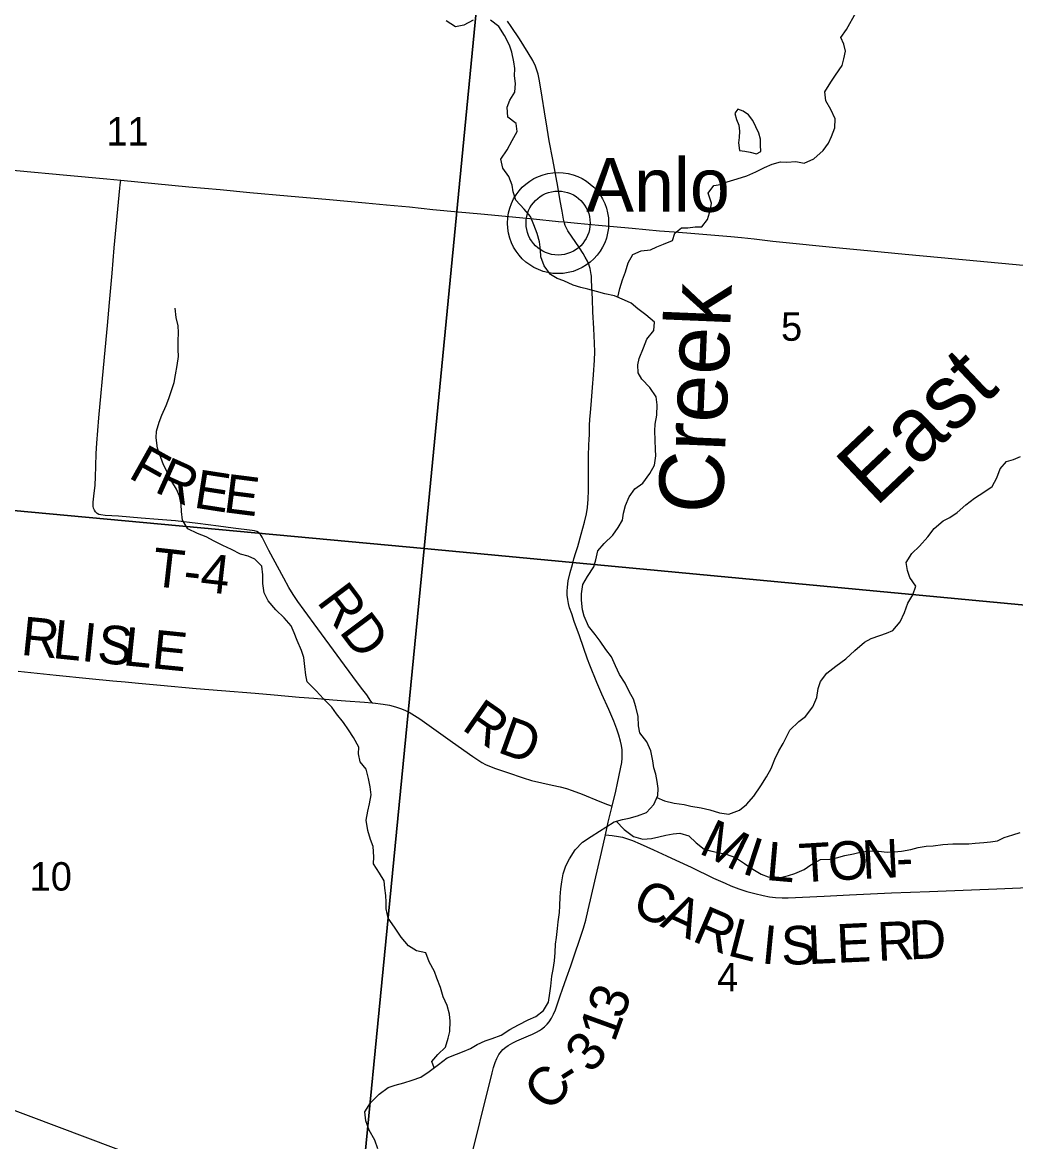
# Model space of a CAD drawing. Extents: x 831 to 1552, y 430 to 870.
# Drawn here: x 1297.57 to 1326.79, y 727.92 to 760.87 of the extents above; entities that cross this region are included whole.
import ezdxf

# ---------------------------------------------------------------- set-up
doc = ezdxf.new("R2010")
doc.units = 0
for name, color, linetype in [('GM_X_Corporation', 7, 'Continuous'), ('GM_X_County_Road', 7, 'Continuous'), ('GM_X_County_Road_Text', 7, 'Continuous'), ('GM_X_Minor_Lake', 7, 'Continuous'), ('GM_X_Minor_River', 7, 'Continuous'), ('GM_X_Minor_River_Text', 7, 'Continuous'), ('GM_X_Section_Text', 7, 'Continuous'), ('GM_X_Township_Road', 7, 'Continuous'), ('GM_X_Township_Road_Text', 7, 'Continuous'), ('GM_X_Unincorporated', 7, 'Continuous'), ('GM_X_Unincorporated_Location', 7, 'Continuous'), ('GM_X_Unincorporated_Text', 7, 'Continuous'), ('SH_Text', 7, 'Continuous')]:
    doc.layers.add(name, color=color, linetype=linetype)

msp = doc.modelspace()

# ---------------------------------------------------------------- linework, layer by layer
at = {"layer": 'GM_X_Corporation'}
for points in [[(1291.379, 767.224), (1311.293, 765.037), (1309.391, 745.383), (1289.554, 747.22)], [(1311.293, 765.037), (1331.382, 763.355), (1329.567, 743.48), (1309.391, 745.383)], [(1289.554, 747.22), (1309.391, 745.383), (1307.365, 724.655), (1287.469, 726.554)], [(1309.391, 745.383), (1329.567, 743.48), (1327.468, 722.912), (1307.365, 724.655)]]:
    msp.add_lwpolyline(points, close=True, dxfattribs=at)
at = {"layer": 'GM_X_County_Road'}
for points in [[(1313.508, 754.996), (1313.49, 755.073), (1313.445, 755.306), (1313.391, 755.611), (1313.32, 756.04), (1313.174, 756.833), (1313.069, 757.382), (1313.007, 757.749), (1312.925, 758.236), (1312.857, 758.668), (1312.783, 759.149), (1312.764, 759.244), (1312.74, 759.343), (1312.707, 759.463), (1312.665, 759.581), (1312.584, 759.745), (1312.446, 759.967), (1312.188, 760.38), (1311.95, 760.751), (1311.842, 760.905)], [(1280.671, 758.126), (1280.82, 758.113), (1281.871, 758.011), (1282.798, 757.914), (1284.097, 757.789), (1285.044, 757.707), (1285.828, 757.627), (1287.312, 757.483), (1288.055, 757.415), (1289.166, 757.314), (1289.731, 757.266), (1290.465, 757.198), (1291.083, 757.133), (1292.012, 757.043), (1292.815, 756.958), (1294.175, 756.821), (1295.782, 756.662), (1296.524, 756.591), (1297.391, 756.511), (1298.875, 756.37), (1300.05, 756.259), (1300.461, 756.22)], [(1300.461, 756.22), (1302.462, 756.031), (1303.39, 755.944), (1304.256, 755.863), (1305.37, 755.762), (1306.607, 755.652), (1307.659, 755.553), (1308.277, 755.494), (1308.957, 755.433), (1309.646, 755.361), (1310.386, 755.29), (1311.052, 755.228), (1312.603, 755.081), (1313.345, 755.011), (1313.508, 754.996)], [(1314.918, 737.795), (1315.023, 738.233), (1315.073, 738.472), (1315.167, 738.896), (1315.204, 739.081), (1315.216, 739.206), (1315.217, 739.332), (1315.209, 739.457), (1315.191, 739.581), (1315.166, 739.704), (1315.115, 739.885), (1315.055, 740.062), (1314.965, 740.294), (1314.819, 740.638), (1314.613, 741.09), (1314.465, 741.431), (1314.262, 741.949), (1314.194, 742.122), (1313.955, 742.809), (1313.804, 743.23), (1313.728, 743.457), (1313.667, 743.633), (1313.633, 743.758), (1313.612, 743.879), (1313.599, 744.002), (1313.597, 744.12), (1313.605, 744.245), (1313.629, 744.431), (1313.684, 744.67), (1313.748, 744.909), (1313.796, 745.076), (1313.851, 745.262), (1313.906, 745.44), (1314.008, 745.804), (1314.107, 746.157), (1314.16, 746.401), (1314.19, 746.586), (1314.213, 746.834), (1314.223, 747.084), (1314.224, 747.457), (1314.227, 748.077), (1314.235, 748.449), (1314.24, 748.573), (1314.249, 748.757), (1314.256, 749.003), (1314.266, 749.188), (1314.283, 749.376), (1314.311, 749.741), (1314.343, 750.117), (1314.372, 750.488), (1314.398, 750.922), (1314.407, 751.172), (1314.403, 751.421), (1314.383, 751.855), (1314.355, 752.347), (1314.338, 752.717), (1314.315, 753.276), (1314.313, 753.338), (1314.307, 753.395), (1314.3, 753.45), (1314.29, 753.507), (1314.279, 753.565), (1314.268, 753.62), (1314.251, 753.685), (1314.228, 753.747), (1314.19, 753.836), (1314.124, 753.961), (1314.067, 754.063), (1313.959, 754.232), (1313.618, 754.734), (1313.584, 754.793), (1313.557, 754.847), (1313.538, 754.891), (1313.518, 754.955), (1313.508, 754.996)], [(1313.508, 754.996), (1313.902, 754.958), (1314.52, 754.899), (1315.51, 754.81), (1316.315, 754.736), (1316.748, 754.701), (1317.119, 754.672), (1318.415, 754.564), (1318.724, 754.536), (1319.094, 754.496), (1319.65, 754.432), (1320.33, 754.363), (1321.009, 754.292), (1321.503, 754.241), (1322.431, 754.151), (1323.544, 754.044), (1324.596, 753.945), (1328.059, 753.623), (1328.678, 753.565), (1329.111, 753.524), (1329.544, 753.485), (1330.044, 753.438), (1330.507, 753.392)], [(1297.445, 741.77), (1298.557, 741.652), (1299.532, 741.552), (1300.225, 741.489), (1300.593, 741.455), (1300.986, 741.418), (1301.632, 741.357), (1302.684, 741.261), (1303.427, 741.202), (1304.414, 741.118), (1304.971, 741.068), (1305.713, 741.007), (1306.146, 740.97), (1306.703, 740.926), (1307.075, 740.899), (1307.63, 740.856), (1307.857, 740.835)], [(1307.857, 740.835), (1307.877, 740.833), (1308.185, 740.799), (1308.367, 740.769), (1308.547, 740.724), (1308.722, 740.664), (1308.835, 740.616), (1308.944, 740.56), (1309.104, 740.466), (1309.259, 740.364), (1310.222, 739.681), (1310.824, 739.256), (1311.084, 739.085), (1311.194, 739.025), (1311.308, 738.972), (1311.483, 738.906), (1311.835, 738.784), (1312.305, 738.626), (1312.544, 738.554), (1312.847, 738.48), (1313.151, 738.418), (1313.393, 738.365), (1313.571, 738.316), (1313.746, 738.256), (1314.034, 738.145), (1314.552, 737.934), (1314.784, 737.846), (1314.918, 737.795)], [(1314.719, 736.953), (1314.805, 737.324), (1314.918, 737.795)], [(1310.828, 727.698), (1310.966, 728.237), (1311.098, 728.77), (1311.241, 729.349), (1311.388, 729.948), (1311.431, 730.101), (1311.479, 730.248), (1311.526, 730.368), (1311.558, 730.431), (1311.588, 730.483), (1311.622, 730.535), (1311.662, 730.583), (1311.706, 730.629), (1311.794, 730.704), (1311.862, 730.752), (1311.992, 730.825), (1312.111, 730.885), (1312.457, 731.03), (1312.572, 731.083), (1312.69, 731.138), (1312.779, 731.188), (1312.843, 731.234), (1312.93, 731.303), (1313.004, 731.374), (1313.068, 731.449), (1313.139, 731.557), (1313.194, 731.672), (1313.248, 731.803), (1313.29, 731.917), (1313.345, 732.064), (1313.393, 732.213), (1313.46, 732.412), (1313.576, 732.741), (1313.699, 733.099), (1313.818, 733.448), (1313.956, 733.855), (1314.073, 734.207), (1314.143, 734.443), (1314.218, 734.743), (1314.409, 735.59), (1314.606, 736.435), (1314.719, 736.953)], [(1314.719, 736.953), (1314.92, 736.93), (1315.103, 736.904), (1315.223, 736.878), (1315.341, 736.845), (1315.514, 736.785), (1315.74, 736.691), (1316.134, 736.513), (1316.517, 736.336), (1316.795, 736.206), (1317.243, 735.996), (1317.905, 735.678), (1318.239, 735.524), (1318.41, 735.451), (1318.642, 735.363), (1318.879, 735.287), (1319.119, 735.221), (1319.36, 735.163), (1319.544, 735.128), (1319.729, 735.103), (1319.916, 735.095), (1320.102, 735.098), (1321.155, 735.15), (1321.898, 735.187), (1323.137, 735.241), (1324.252, 735.285), (1325.491, 735.329), (1326.234, 735.361), (1328.329, 735.448)]]:
    msp.add_lwpolyline(points, dxfattribs=at)
at = {"layer": 'GM_X_Minor_Lake'}
for points in [[(1318.56, 758.235), (1318.525, 758.19), (1318.576, 758.007), (1318.642, 757.839), (1318.67, 757.664), (1318.66, 757.481), (1318.635, 757.322), (1318.663, 757.094)], [(1318.663, 757.094), (1318.822, 757.077), (1318.981, 757.044), (1319.163, 756.997), (1319.293, 757.071), (1319.28, 757.254), (1319.282, 757.428), (1319.232, 757.604), (1319.15, 757.795), (1319.054, 757.978), (1318.927, 758.147), (1318.776, 758.255), (1318.617, 758.31), (1318.56, 758.235)]]:
    msp.add_lwpolyline(points, dxfattribs=at)
at = {"layer": 'GM_X_Minor_River'}
for points in [[(1315.084, 752.779), (1315.147, 753.032), (1315.219, 753.289), (1315.313, 753.524), (1315.392, 753.789), (1315.532, 754.038), (1315.777, 754.141), (1316.043, 754.169), (1316.234, 754.257), (1316.433, 754.339), (1316.692, 754.45), (1316.763, 754.662), (1316.955, 754.819), (1317.145, 754.824), (1317.358, 754.852), (1317.556, 754.85), (1317.726, 755.068), (1317.813, 755.356), (1317.838, 755.546), (1317.743, 755.843), (1317.913, 756.069), (1318.103, 756.097), (1318.302, 756.178), (1318.599, 756.266), (1318.881, 756.346), (1319.149, 756.472), (1319.401, 756.598), (1319.623, 756.695), (1319.867, 756.76), (1320.056, 756.75), (1320.323, 756.777), (1320.565, 756.721), (1320.855, 756.847), (1321.124, 757.095), (1321.287, 757.313), (1321.373, 757.51), (1321.467, 757.767), (1321.478, 758.033), (1321.352, 758.3), (1321.204, 758.561), (1321.177, 758.827), (1321.355, 759.106), (1321.487, 759.317), (1321.688, 759.596), (1321.736, 759.793), (1321.784, 760.02), (1321.734, 760.226), (1321.645, 760.425), (1321.815, 760.659), (1322.095, 761.172)], [(1310.826, 760.928), (1310.558, 760.787), (1310.307, 760.736), (1310.035, 760.915)], [(1314.224, 743.093), (1314.099, 743.384), (1314.048, 743.574), (1314.013, 743.856), (1314.016, 744.046), (1314.057, 744.319), (1314.189, 744.56), (1314.383, 744.839), (1314.439, 745.051), (1314.495, 745.309), (1314.688, 745.527), (1314.934, 745.775), (1315.096, 745.994), (1315.221, 746.213), (1315.254, 746.417), (1315.31, 746.645), (1315.419, 746.902), (1315.589, 747.135), (1315.819, 747.308), (1316.028, 747.586), (1316.16, 747.835), (1316.202, 748.109), (1316.197, 748.299), (1316.173, 748.846), (1316.183, 749.044), (1316.232, 749.309), (1316.244, 749.605), (1316.209, 749.849), (1316.03, 750.117), (1315.79, 750.363), (1315.686, 750.555), (1315.673, 750.783), (1315.714, 750.972), (1315.839, 751.29), (1315.941, 751.547), (1316.142, 751.796), (1316.168, 752.046), (1315.912, 752.262), (1315.672, 752.44), (1315.476, 752.602), (1315.28, 752.695), (1314.985, 752.821), (1314.705, 752.877), (1314.463, 752.949), (1314.205, 753.012), (1314.001, 753.06), (1313.774, 753.132), (1313.502, 753.257), (1313.305, 753.327), (1313.109, 753.444), (1312.915, 753.697), (1312.819, 753.964), (1312.814, 754.169), (1312.779, 754.405), (1312.714, 754.657), (1312.611, 754.909), (1312.515, 755.153), (1312.328, 755.369), (1312.088, 755.63), (1312.008, 755.882), (1311.98, 756.072), (1311.877, 756.332), (1311.698, 756.577), (1311.64, 756.844), (1311.826, 757.115), (1311.981, 757.395), (1312.121, 757.651), (1312.094, 757.895), (1311.853, 758.08), (1311.827, 758.369), (1311.905, 758.574), (1312.06, 758.815), (1312.078, 759.066), (1312.043, 759.294), (1312.054, 759.507), (1312.026, 759.705), (1311.969, 759.994), (1311.895, 760.193), (1311.754, 760.483), (1311.583, 760.751), (1311.342, 760.929)], [(1309.683, 730.096), (1309.618, 730.284), (1309.788, 730.487), (1310.011, 730.704), (1310.09, 730.962), (1310.139, 731.166), (1310.15, 731.462), (1310.137, 731.675), (1310.064, 731.927), (1309.946, 732.187), (1309.866, 732.461), (1309.763, 732.736), (1309.69, 732.927), (1309.534, 733.21), (1309.438, 733.477), (1309.158, 733.541), (1308.924, 733.68), (1308.715, 733.941), (1308.513, 734.232), (1308.327, 734.5), (1308.269, 734.775), (1308.272, 734.972), (1308.259, 735.17), (1308.231, 735.383), (1308.211, 735.596), (1308.07, 735.826), (1307.898, 736.094), (1307.909, 736.306), (1307.89, 736.61), (1307.809, 736.816), (1307.728, 737.083), (1307.679, 737.388), (1307.735, 737.646), (1307.784, 737.865), (1307.825, 738.131), (1307.798, 738.367), (1307.755, 738.61), (1307.683, 738.885), (1307.503, 739.1), (1307.46, 739.336), (1307.463, 739.533), (1307.307, 739.816), (1307.165, 740.039), (1307.016, 740.261), (1306.807, 740.514), (1306.672, 740.706), (1306.425, 740.959), (1306.215, 741.19), (1305.945, 741.451), (1305.909, 741.649), (1305.882, 741.908), (1305.848, 742.167), (1305.782, 742.373), (1305.656, 742.671), (1305.568, 742.9), (1305.48, 743.106), (1305.27, 743.344), (1305.022, 743.575), (1304.797, 743.836), (1304.679, 744.073), (1304.637, 744.347), (1304.64, 744.606), (1304.613, 744.864), (1304.41, 745.065), (1304.206, 745.151), (1303.987, 745.214), (1303.723, 745.354), (1303.466, 745.471), (1303.209, 745.596), (1302.975, 745.72), (1302.718, 745.822), (1302.439, 745.962), (1302.282, 746.215), (1302.248, 746.474), (1302.243, 746.671), (1302.193, 746.923), (1302.097, 747.129), (1301.963, 747.351), (1301.867, 747.558), (1301.718, 747.84), (1301.637, 748.062), (1301.542, 748.329), (1301.508, 748.634), (1301.518, 748.839), (1301.59, 749.096), (1301.668, 749.301), (1301.794, 749.588), (1301.872, 749.792), (1301.959, 750.027), (1302.03, 750.269), (1302.071, 750.497), (1302.12, 750.77), (1302.161, 751.028), (1302.149, 751.241), (1302.152, 751.484), (1302.163, 751.735), (1302.15, 751.933), (1302.092, 752.177), (1302.065, 752.451)], [(1316.23, 738.049), (1316.461, 737.952), (1316.742, 737.888), (1317.037, 737.846), (1317.234, 737.798), (1317.537, 737.742), (1317.795, 737.685), (1318.075, 737.598), (1318.356, 737.564), (1318.661, 737.682), (1318.868, 737.847), (1319.092, 738.088), (1319.293, 738.389), (1319.456, 738.661), (1319.596, 738.902), (1319.705, 739.175), (1319.823, 739.424), (1319.947, 739.643), (1320.149, 740.036), (1320.411, 740.291), (1320.61, 740.433), (1320.819, 740.719), (1320.936, 740.999), (1320.978, 741.257), (1321.049, 741.469), (1321.234, 741.71), (1321.503, 741.919), (1321.794, 742.136), (1322.063, 742.376), (1322.34, 742.624), (1322.538, 742.735), (1322.798, 742.823), (1322.989, 742.889), (1323.18, 742.971), (1323.395, 743.219), (1323.521, 743.499), (1323.615, 743.771), (1323.763, 744.02), (1323.849, 744.27), (1323.678, 744.53), (1323.604, 744.729), (1323.569, 744.965), (1323.732, 745.229), (1323.963, 745.447), (1324.21, 745.725), (1324.395, 745.973), (1324.656, 746.191), (1324.855, 746.295), (1325.069, 746.437), (1325.323, 746.669), (1325.584, 746.864), (1325.852, 747.043), (1326.097, 747.207), (1326.237, 747.464), (1326.339, 747.721), (1326.524, 747.939), (1326.73, 748.005), (1326.936, 748.086)], [(1308.029, 727.704), (1307.941, 727.964), (1307.77, 728.262), (1307.674, 728.537), (1307.647, 728.795), (1307.81, 729.059), (1308.064, 729.322), (1308.332, 729.509), (1308.531, 729.582), (1308.79, 729.655), (1309.034, 729.728), (1309.286, 729.817), (1309.531, 729.981), (1309.807, 730.19), (1310.068, 730.385), (1310.335, 730.495), (1310.564, 730.584), (1310.755, 730.658), (1310.947, 730.777), (1311.183, 730.888), (1311.389, 730.954), (1311.649, 731.057), (1311.909, 731.221), (1312.162, 731.355), (1312.452, 731.503), (1312.674, 731.6), (1312.897, 731.779), (1313.044, 732.021), (1313.085, 732.294), (1313.111, 732.498), (1313.145, 732.787), (1313.185, 732.991), (1313.226, 733.242), (1313.245, 733.485), (1313.255, 733.735), (1313.281, 733.932), (1313.307, 734.198), (1313.332, 734.395), (1313.373, 734.668), (1313.376, 734.858), (1313.394, 735.124), (1313.412, 735.359), (1313.438, 735.564), (1313.479, 735.799), (1313.558, 736.041), (1313.667, 736.245), (1313.83, 736.509), (1314.045, 736.735), (1314.298, 736.899), (1314.543, 737.055), (1314.735, 737.182), (1314.98, 737.331), (1315.224, 737.404), (1315.422, 737.44), (1315.665, 737.506), (1315.933, 737.609), (1316.141, 737.842), (1316.258, 738.114), (1316.276, 738.319), (1316.24, 738.525), (1316.205, 738.738), (1316.147, 738.928), (1316.111, 739.134), (1316.054, 739.423), (1315.936, 739.691), (1315.734, 739.952), (1315.691, 740.165), (1315.687, 740.431), (1315.615, 740.721), (1315.549, 740.942), (1315.43, 741.156), (1315.304, 741.416), (1315.133, 741.676), (1315.022, 741.928), (1314.896, 742.188), (1314.732, 742.403), (1314.568, 742.656), (1314.418, 742.848), (1314.224, 743.093)], [(1315.041, 737.35), (1315.273, 737.108), (1315.544, 736.899), (1315.817, 736.827), (1316.075, 736.84), (1316.288, 736.89), (1316.494, 736.941), (1316.715, 736.984), (1316.913, 736.997), (1317.17, 736.925), (1317.388, 736.717), (1317.628, 736.525), (1317.856, 736.469), (1318.075, 736.42), (1318.272, 736.38), (1318.545, 736.286), (1318.816, 736.108), (1319.057, 735.945), (1319.306, 735.79), (1319.51, 735.712), (1319.722, 735.679), (1319.913, 735.707), (1320.103, 735.758), (1320.294, 735.816), (1320.569, 735.935), (1320.76, 736.069), (1321.051, 736.225), (1321.325, 736.237), (1321.515, 736.273), (1321.767, 736.346), (1322.018, 736.388), (1322.216, 736.439), (1322.49, 736.481), (1322.756, 736.471), (1323.006, 736.445), (1323.219, 736.45), (1323.432, 736.47), (1323.706, 736.52), (1323.92, 736.578), (1324.156, 736.613), (1324.361, 736.626), (1324.643, 736.668), (1324.939, 736.687), (1325.137, 736.685), (1325.41, 736.689), (1325.6, 736.702), (1325.851, 736.722), (1326.049, 736.743), (1326.255, 736.778), (1326.453, 736.874), (1326.705, 736.947), (1326.919, 737.021)]]:
    msp.add_lwpolyline(points, dxfattribs=at)
at = {"layer": 'GM_X_Township_Road'}
msp.add_lwpolyline([(1307.857, 740.835), (1307.822, 740.885), (1307.697, 741.069), (1307.588, 741.219), (1307.401, 741.466), (1306.26, 743.014), (1305.857, 743.565), (1305.676, 743.817), (1305.536, 744.022), (1305.408, 744.234), (1305.255, 744.504), (1304.817, 745.325), (1304.619, 745.712), (1304.596, 745.761), (1304.561, 745.813), (1304.512, 745.854), (1304.466, 745.88), (1304.397, 745.897), (1304.33, 745.911), (1303.77, 745.978), (1303.34, 746.033), (1302.727, 746.114), (1302.069, 746.192), (1301.566, 746.238), (1301.066, 746.278), (1300.393, 746.33), (1300.002, 746.356), (1299.879, 746.369), (1299.819, 746.385), (1299.764, 746.413), (1299.718, 746.455), (1299.685, 746.506), (1299.664, 746.564), (1299.654, 746.625), (1299.651, 746.686), (1299.654, 746.749), (1299.671, 746.925), (1299.705, 747.244), (1299.72, 747.491), (1299.731, 747.802), (1299.734, 748.174), (1299.753, 748.483), (1299.818, 749.225), (1299.983, 751.017), (1300.068, 751.944), (1300.128, 752.624), (1300.204, 753.49), (1300.272, 754.231), (1300.438, 755.985), (1300.448, 756.085), (1300.461, 756.22)], dxfattribs=at)
at = {"layer": 'GM_X_Unincorporated'}
for radius in [1.488, 0.943]:
    msp.add_circle((1313.328, 754.96), radius, dxfattribs=at)
at = {"layer": 'GM_X_Unincorporated_Location'}
msp.add_line((1313.328, 754.96), (1313.328, 754.96), dxfattribs=at)
at = {"layer": 'SH_Text'}
msp.add_lwpolyline([(1309.717, 724.179), (1213.915, 750.822), (1213.915, 760.257)], close=True, dxfattribs=at)

# ---------------------------------------------------------------- texts
at = {"layer": 'GM_X_County_Road_Text'}
for s, rotation, p in [('R', 354.1972, (1297.5, 742.253)), ('L', 354.1918, (1298.429, 742.159)), ('I', 354.1951, (1299.275, 742.073)), ('S', 354.1934, (1299.739, 742.025)), ('L', 354.194, (1300.502, 741.948)), ('E', 354.196, (1301.347, 741.862)), ('R', 325.1679, (1310.46, 740.075)), ('D', 340.127, (1311.508, 739.396)), ('M', 334.1575, (1317.433, 736.427)), ('I', 341.9086, (1318.699, 735.827)), ('L', 355.0031, (1319.419, 735.625)), ('T', 3.4558, (1320.449, 735.549)), ('O', 2.901, (1321.295, 735.6)), ('N', 2.8971, (1322.293, 735.65)), ('-', 2.9001, (1323.292, 735.701)), ('C', 335.0305, (1315.445, 734.672)), ('A', 335.2699, (1316.296, 734.276)), ('R', 336.7949, (1317.235, 733.844)), ('L', 345.6058, (1318.273, 733.415)), ('R', 2.6903, (1322.741, 733.239)), ('D', 2.6909, (1323.674, 733.283)), ('I', 354.5179, (1319.286, 733.171)), ('S', 1.6683, (1319.905, 733.121)), ('L', 2.6329, (1320.692, 733.144)), ('E', 2.6796, (1321.543, 733.183)), ('3', 70.5976, (1315.228, 731.483)), ('1', 70.0619, (1314.986, 730.814)), ('3', 48.968, (1314.296, 729.894)), ('C', 50.0765, (1313.099, 728.756)), ('-', 32.2751, (1313.628, 729.411))]:
    msp.add_text(s, height=1.136, rotation=rotation, dxfattribs=at).set_placement(p)
at = {"layer": 'GM_X_Minor_River_Text'}
for s, height, rotation, p in [('Creek', 1.8952, 87.6381, (1318.164, 746.384)), ('East', 1.8946, 43.428, (1322.669, 746.574))]:
    msp.add_text(s, height=height, rotation=rotation, dxfattribs=at).set_placement(p)
at = {"layer": 'GM_X_Section_Text'}
for s, height, p in [('11', 0.8371, (1300.037, 757.243)), ('5', 0.837, (1319.887, 751.495)), ('10', 0.8371, (1297.779, 735.31)), ('4', 0.837, (1318.004, 732.341))]:
    msp.add_text(s, height=height, rotation=0, dxfattribs=at).set_placement(p)
at = {"layer": 'GM_X_Township_Road_Text'}
for s, height, rotation, p in [('F', 1.136, 330.7737, (1300.65, 747.486)), ('R', 1.136, 335.9222, (1301.417, 747.062)), ('E', 1.136, 351.1931, (1302.58, 746.59)), ('E', 1.136, 352.732, (1303.452, 746.455)), ('T-4', 1.1364, 353.559, (1301.344, 744.283)), ('RD', 1.1364, 306.8728, (1306.207, 743.81))]:
    msp.add_text(s, height=height, rotation=rotation, dxfattribs=at).set_placement(p)
at = {"layer": 'GM_X_Unincorporated_Text'}
msp.add_text('Anlo', height=1.5795, rotation=0, dxfattribs=at).set_placement((1314.154, 755.291))

doc.saveas('drawing.dxf')
